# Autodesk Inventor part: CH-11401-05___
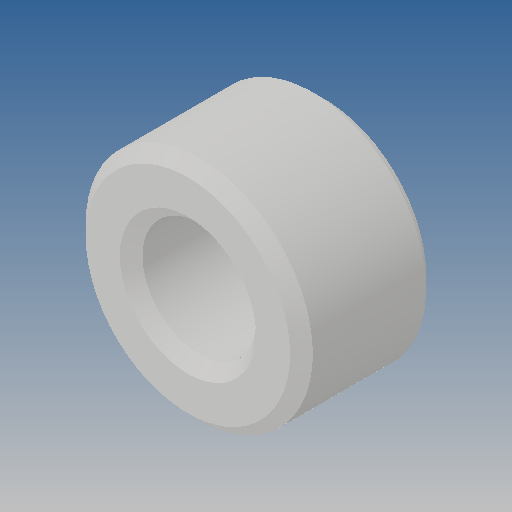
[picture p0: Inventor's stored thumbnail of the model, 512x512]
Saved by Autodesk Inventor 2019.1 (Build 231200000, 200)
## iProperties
Created: 2012-09
Part Number: CH-11401-05___
Material: Ogólny
Document SubType Name: Modeling
Designer: CADENGINEERING4
Density: 1 g/cm^3
Appearance: Domyślna
Author: CADENGINEERING4
Revision Number: ÈÎºÎ
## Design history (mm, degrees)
feature "NONE"
node "Bryła1"
